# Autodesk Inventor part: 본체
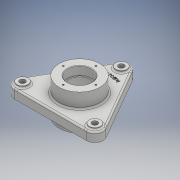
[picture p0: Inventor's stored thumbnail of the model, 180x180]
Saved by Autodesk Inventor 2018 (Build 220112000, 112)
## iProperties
Created: 2023-04
Part Number: 본체
Material: 일반
Document SubType Name: Modeling
Designer: 강의실04
Density: 1 g/cm^3
Appearance: 기본값
Author: 강의실04
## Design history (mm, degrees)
sketch "스케치1"
  geometry: C1 r 40 at (0, 0); 1 further point
  constraints: 1 centre point, 1 coincident
  dimensions: "d0" = 80 diameter of C1
extrude "돌출1" new body sketch "스케치1" distance "d1" = 18; taper "d2" = 0 deg
sketch "스케치2"
  geometry: C1 r 45 at (0, 0); 1 further point
  constraints: 1 centre point, 1 coincident
  dimensions: "d3" = 90 diameter of C1
extrude "돌출2" join sketch "스케치2" distance "d4" = 5; taper "d5" = 0 deg
sketch "스케치3" dims "d6" = 114
  geometry: L1 (-98.727, -57)-(0, 114); L2 (0, 114)-(98.727, -57); L3 (98.727, -57)-(-98.727, -57); 4 further points
  constraints: 6 end point, 2 coincident, 1 midpoint, 1 vertical alignment, 9 other
extrude "돌출3" join sketch "스케치3" distance "d7" = 18; taper "d8" = 0 deg
sketch "스케치4"
  geometry: C1 r 40 at (0, 0) reference; C2 r 40 at (0, 0); 1 further point
  constraints: 1 centre point, 1 coincident
  dimensions: "d9" = 80 diameter of C2
extrude "돌출4" join sketch "스케치4" distance "d10" = 29; taper "d11" = 0 deg
sketch "스케치5"
  geometry: C1 r 21 at (0, 0); 1 further point
  constraints: 1 centre point, 1 coincident
  dimensions: "d12" = 42 diameter of C1
extrude "돌출5" cut sketch "스케치5" extent not by distance; stored distance "d13" = 29; taper "d14" = 0 deg
sketch "스케치6"
  geometry: C1 r 23.5 at (0, 0); 1 further point
  constraints: 1 centre point, 1 coincident
  dimensions: "d15" = 47 diameter of C1
extrude "돌출6" cut sketch "스케치6" distance "d16" = 17; taper "d17" = 0 deg
sketch "스케치7"
  geometry: C1 r 23.5 at (0, 0); 1 further point
  constraints: 1 centre point, 1 coincident
  dimensions: "d18" = 47 diameter of C1
extrude "돌출7" cut sketch "스케치7" distance "d19" = 17; taper "d20" = 0 deg
fillet "모깎기1" dims "d21" = 16
sketch "스케치8" dims "d22" = 164
  geometry: C1 r 11 at (0, 82); 2 further points
  constraints: 1 centre point, 1 coincident, 1 vertical alignment, 2 other
  dimensions: "d23" = 22 diameter of C1
extrude "돌출8" join sketch "스케치8" distance "d24" = 4; taper "d25" = 0 deg
sketch "스케치9"
  geometry: C1 r 5.5 at (0, 0); 1 further point
  constraints: 1 centre point
  dimensions: "d26" = 11 diameter of C1
extrude "돌출9" cut sketch "스케치9" extent not by distance; stored distance "d27" = 4; taper "d28" = 0 deg
sketch "스케치10" dims "d29" = 64
  geometry: 3 further points
  constraints: 2 vertical alignment, 1 coincident, 2 other
hole "구멍1" sketch "스케치10" at (0, 32) diameter "d30" = 3.242; stored, may be unused: countersink angle "d34" = 90 deg, drill point angle "d36" = 118 deg; dims "d31" = 8, "d32" = 9.4, "d33" = 2, "d35" = 10
sketch "스케치11"
  geometry: C1 r 32 at (0, 0); C2 r 1.621 at (0, 32) reference; 2 further points
  constraints: 2 coincident, 1 centre point
  dimensions: "d40" = 64 diameter of C1
hole "구멍2" sketch "스케치11" at (0, 32) diameter "d41" = 3.242; stored, may be unused: countersink angle "d45" = 90 deg, drill point angle "d47" = 118 deg; dims "d42" = 8, "d43" = 9.4, "d44" = 2, "d46" = 10
fillet "모깎기2" dims "d51" = 3
fillet "모깎기3" dims "d55" = 3
chamfer "모따기1" distance "d56" = 1; stored, may be unused: second distance "d57" = 2, angle "d58" = 45 deg
chamfer "모따기2" distance "d59" = 1; stored, may be unused: second distance "d60" = 2, angle "d61" = 45 deg
fillet "모깎기4" dims "d62" = 0.6
sketch "스케치12"
  geometry: C1 r 57 at (0, 0); 1 further point
  constraints: 1 centre point, 1 coincident, 1 other
  dimensions: "d63" = 114 diameter of C1
feature "엠보싱1" sketch "스케치12" dims "d9" = 80, "d64" = 0.5, "d65" = 0
node "솔리드1"
pattern_circular "원형 패턴1" dims angle "d38" = 360 deg
pattern_circular "원형 패턴2" dims angle "d49" = 360 deg
pattern_circular "원형 패턴3" dims angle "d53" = 360 deg
